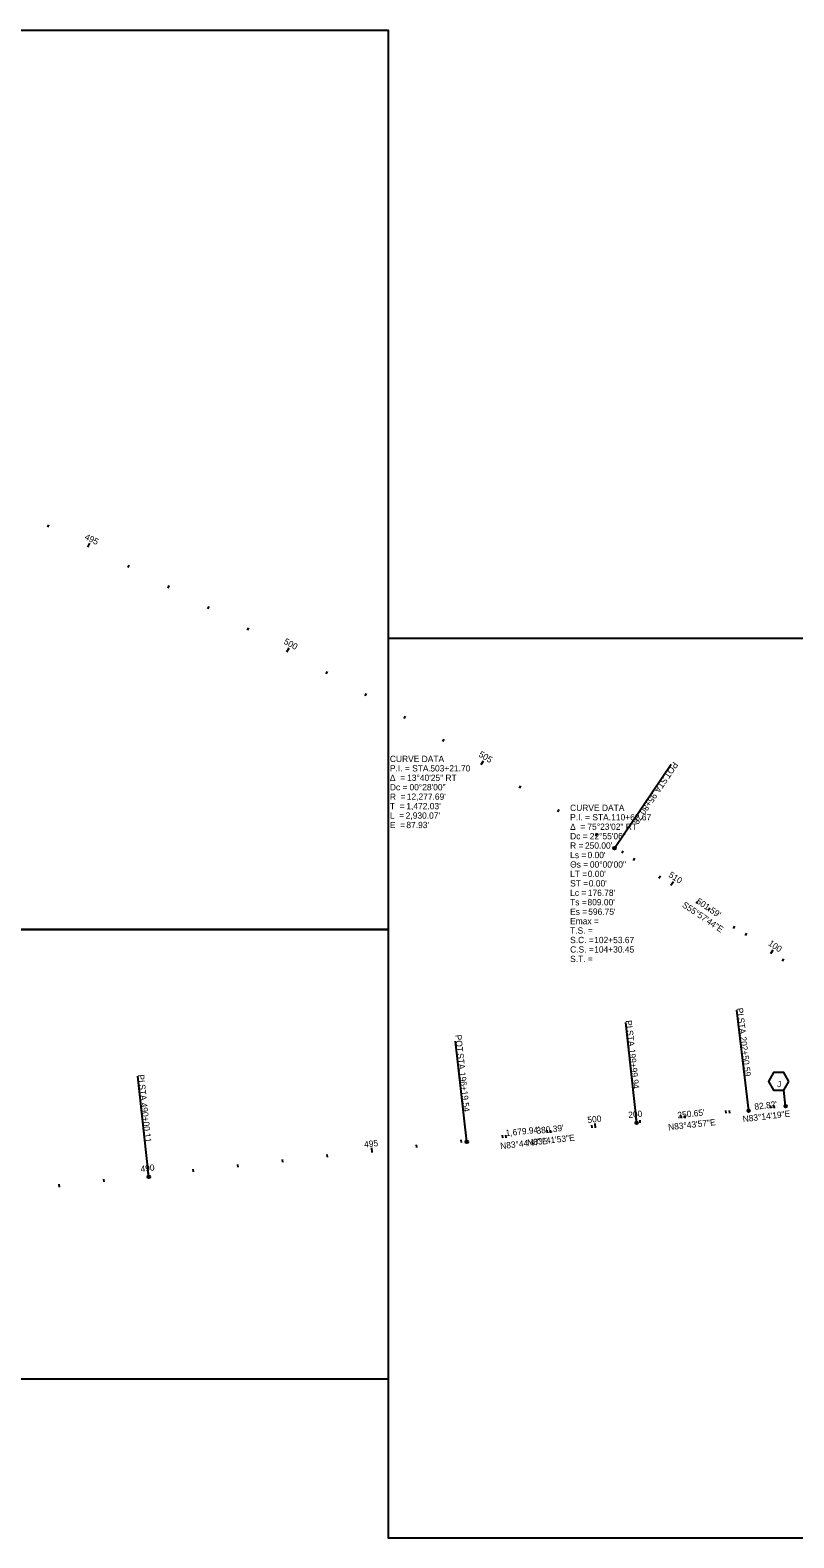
# Model space of a CAD drawing. Extents: x 1597353 to 1604853, y 283653 to 289007.
# Drawn here: x 1599057 to 1600756, y 285653 to 289007 of the extents above; entities that cross this region are included whole.
import ezdxf

# ---------------------------------------------------------------- set-up
doc = ezdxf.new("R2010")
doc.units = 0
for name, color, linetype in [('_CIVIL_CONSTRUCTION', 7, 'Continuous'), ('GE_X_Alignment_100_Cardinal_Points', 7, 'Continuous'), ('GE_X_Alignment_100_Curve_Data', 7, 'Continuous'), ('GE_X_Alignment_100_Distances', 7, 'Continuous'), ('GE_X_Alignment_100_Stations', 7, 'Continuous'), ('SH_Border', 7, 'Continuous'), ('SH_Cut_Line', 7, 'Continuous'), ('SH_Data', 7, 'Continuous'), ('SH_Masking', 7, 'Continuous'), ('SH_Named_Boundary', 7, 'Continuous'), ('SH_Text', 7, 'Continuous'), ('SV_X_Control_Cells_Found', 7, 'Continuous')]:
    doc.layers.add(name, color=color, linetype=linetype)

msp = doc.modelspace()

# ---------------------------------------------------------------- linework, layer by layer
at = {"layer": '_CIVIL_CONSTRUCTION'}
msp.add_line((1599853.4, 286006.5), (1597353.4, 286006.5), dxfattribs=at)
for points in [[(1597353.4, 289006.5), (1599853.4, 289006.5), (1599853.4, 287006.5), (1597353.4, 287006.5)], [(1599853.4, 287653.4), (1599853.4, 285653.4), (1600103.4, 285653.4), (1600353.4, 285653.4), (1600603.4, 285653.4), (1600853.4, 285653.4), (1601103.4, 285653.4), (1601353.4, 285653.4), (1601603.4, 285653.4), (1601853.4, 285653.4), (1602103.4, 285653.4), (1602353.4, 285653.4), (1602353.4, 287653.4), (1602103.4, 287653.4), (1601853.4, 287653.4), (1601603.4, 287653.4), (1601353.4, 287653.4), (1601103.4, 287653.4), (1600853.4, 287653.4), (1600603.4, 287653.4), (1600353.4, 287653.4), (1600103.4, 287653.4)]]:
    msp.add_lwpolyline(points, close=True, dxfattribs=at)
msp.add_lwpolyline([(1597353.4, 286006.5), (1597353.4, 287006.5), (1599853.4, 287006.5), (1599853.4, 286006.5)], dxfattribs=at)
at = {"layer": 'GE_X_Alignment_100_Curve_Data'}
msp.add_line((1599320.8, 286456.2), (1599296.3, 286679.9), dxfattribs=at)
msp.add_circle((1599320.8, 286456.2), 3, dxfattribs=at)
at = {"layer": 'GE_X_Alignment_100_Stations'}
for p, q in [((1599095.7, 287901.1), (1599098.3, 287906.5)), ((1599185.3, 287856.7), (1599189.8, 287865.7)), ((1599274.5, 287811.6), (1599277.3, 287816.9)), ((1599363.4, 287765.7), (1599366.2, 287771.1)), ((1599451.9, 287719.2), (1599454.7, 287724.5)), ((1599540, 287671.9), (1599542.9, 287677.1)), ((1599627.7, 287623.9), (1599632.6, 287632.6)), ((1599715.1, 287575.1), (1599718, 287580.4)), ((1599802, 287525.7), (1599805, 287530.9)), ((1599888.5, 287475.6), (1599891.5, 287480.7)), ((1599974.6, 287424.7), (1599977.7, 287429.9)), ((1600060.3, 287373.2), (1600065.5, 287381.7)), ((1600145.6, 287320.9), (1600148.7, 287326)), ((1600230.4, 287268), (1600233.6, 287273.1)), ((1600314.8, 287214.4), (1600318.1, 287219.4)), ((1600398.8, 287160.1), (1600402.1, 287165.1)), ((1600482.3, 287105.1), (1600487.9, 287113.4)), ((1600565.4, 287049.4), (1600568.8, 287054.4)), ((1600648, 286993.1), (1600651.4, 286998)), ((1600730.2, 286936.1), (1600733.6, 286941)), ((1600613, 286597.8), (1600612.3, 286603.7)), ((1600712.4, 286608.7), (1600711.7, 286614.6)), ((1600314.8, 286565.1), (1600313.7, 286575)), ((1600414.2, 286576), (1600413.5, 286582)), ((1600513.6, 286586.9), (1600512.9, 286592.9)), ((1600016.6, 286532.4), (1600015.9, 286538.4)), ((1600116, 286543.3), (1600115.3, 286549.3)), ((1600215.4, 286554.2), (1600214.7, 286560.2)), ((1599718.3, 286499.7), (1599717.7, 286505.7)), ((1599817.8, 286510.6), (1599816.7, 286520.6)), ((1599917.2, 286521.5), (1599916.5, 286527.5)), ((1599320.7, 286456.2), (1599319.6, 286466.1)), ((1599420.1, 286467.1), (1599419.5, 286473)), ((1599519.5, 286478), (1599518.9, 286483.9)), ((1599618.9, 286488.9), (1599618.3, 286494.8)), ((1599122, 286433.6), (1599121.3, 286439.6)), ((1599221.4, 286444.9), (1599220.7, 286450.9))]:
    msp.add_line(p, q, dxfattribs=at)
at = {"layer": 'SH_Border'}
for p, q in [((1600356.9, 287187.3), (1600482.8, 287373.8)), ((1600406.1, 286576.1), (1600381.6, 286799.7)), ((1600655.3, 286603.4), (1600628.8, 286826.9)), ((1600028, 286534.3), (1600003.3, 286758)), ((1600737.5, 286613.2), (1600733.3, 286648.7))]:
    msp.add_line(p, q, dxfattribs=at)
msp.add_lwpolyline([(1600744.6, 286668.3), (1600733.3, 286688), (1600710.6, 286688), (1600699.3, 286668.3), (1600710.6, 286648.7), (1600733.3, 286648.7)], close=True, dxfattribs=at)
for centre in [(1600356.9, 287187.3), (1600655.3, 286603.4), (1600406.1, 286576.1), (1600028, 286534.3)]:
    msp.add_circle(centre, 3, dxfattribs=at)
at = {"layer": 'SH_Text'}
for p, q in [((1600372.8, 287176.6), (1600376.2, 287181.5)), ((1600455.7, 287120.6), (1600459, 287125.6)), ((1600538.5, 287064.6), (1600541.9, 287069.6)), ((1600621.4, 287008.6), (1600624.8, 287013.6)), ((1600704.3, 286952.7), (1600709.9, 286961)), ((1600605, 286597.9), (1600604.3, 286603.9)), ((1600704.4, 286609.2), (1600703.6, 286615.2)), ((1600306.8, 286565.1), (1600306.1, 286571.1)), ((1600406.2, 286576.1), (1600405.1, 286586)), ((1600505.6, 286587), (1600504.9, 286593)), ((1600108, 286543.1), (1600107.3, 286549.1)), ((1600207.4, 286554.1), (1600206.7, 286560.1))]:
    msp.add_line(p, q, dxfattribs=at)
at = {"layer": 'SV_X_Control_Cells_Found'}
msp.add_circle((1600737.5, 286613.2), 3, dxfattribs=at)

# ---------------------------------------------------------------- texts
at = {"layer": 'GE_X_Alignment_100_Cardinal_Points'}
msp.add_text('N83°44\'47"E', height=14, rotation=6.2535, dxfattribs=at).set_placement((1600103.2, 286517.8))
at = {"layer": 'GE_X_Alignment_100_Curve_Data'}
for s, p in [('PI', (1599296.2, 286683.1)), (' STA. ', (1599298, 286666.6)), ('490+00.11', (1599303, 286620.3))]:
    msp.add_text(s, height=14, rotation=276.2535, dxfattribs=at).set_placement(p)
at = {"layer": 'GE_X_Alignment_100_Distances'}
msp.add_text("1,679.94'", height=14, rotation=6.2535, dxfattribs=at).set_placement((1600115.2, 286546.4))
at = {"layer": 'GE_X_Alignment_100_Stations'}
for s, rotation, p in [('495', 333.408, (1599176.6, 287875.1)), ('500', 331.0747, (1599619.5, 287642.7)), ('505', 328.7414, (1600053.1, 287392.2)), ('510', 326.4081, (1600475.6, 287124.5)), ('500', 6.2535, (1600297.2, 286575.8)), ('495', 6.2535, (1599800.4, 286521.3)), ('490', 6.4702, (1599303.1, 286466.8))]:
    msp.add_text(s, height=14, rotation=rotation, dxfattribs=at).set_placement(p)
at = {"layer": 'SH_Border'}
for s, rotation, p in [('POT', 235.9623, (1600487.7, 287380.6)), (' STA. ', 235.9623, (1600467.5, 287350.7)), ('95+80.78', 235.9623, (1600441.1, 287311.6)), ('PI', 276.7614, (1600628.5, 286831.2)), ('PI', 276.2675, (1600381.3, 286803.8)), (' STA. ', 276.7614, (1600630.5, 286814.4)), ('POT', 276.3018, (1600002.1, 286771.5)), (' STA. ', 276.2675, (1600383.2, 286787)), ('202+50.59', 276.7614, (1600636, 286767.4)), (' STA. ', 276.3018, (1600006, 286735.7)), ('199+99.94', 276.2675, (1600388.3, 286740)), ('196+19.54', 276.3018, (1600011.2, 286688.8))]:
    msp.add_text(s, height=14, rotation=rotation, dxfattribs=at).set_placement(p)
msp.add_text('J', height=14, dxfattribs=at).set_placement((1600718.5, 286655.7))
at = {"layer": 'SH_Cut_Line'}
for s, rotation, p in [('S55°57\'44"E', 325.9623, (1600505.9, 287057.7)), ('N83°14\'19"E', 6.7614, (1600642.8, 286577.8)), ('N83°43\'57"E', 6.2675, (1600476.8, 286559.7)), ('N83°41\'53"E', 6.3018, (1600163.2, 286525.1))]:
    msp.add_text(s, height=14, rotation=rotation, dxfattribs=at).set_placement(p)
at = {"layer": 'SH_Data'}
for s, p in [('CURVE DATA', (1600258, 287270)), ('Δ  = ', (1600258, 287228)), ('P.I. = STA. ', (1600258, 287249)), ('75°23\'02" RT', (1600296.4, 287228)), ('110+62.67', (1600349.4, 287249)), ('Dc = ', (1600258, 287207)), ('R = ', (1600258, 287186)), ("250.00'", (1600291, 287186)), ('22°55\'06"', (1600301.7, 287207)), ('Ls = ', (1600258, 287165)), ("0.00'", (1600296.8, 287165)), ('Θs = ', (1600258, 287144)), ('LT = ', (1600258, 287123)), ("0.00'", (1600297.3, 287123)), ('00°00\'00"', (1600302, 287144)), ('ST = ', (1600258, 287102)), ("0.00'", (1600299.6, 287102)), ('Ts = ', (1600258, 287060)), ('Lc = ', (1600258, 287081)), ("809.00'", (1600296.7, 287060)), ("176.78'", (1600297.4, 287081)), ('Es = ', (1600258, 287039)), ('Emax = ', (1600258, 287018)), ("596.75'", (1600298.3, 287039)), ('T.S. = ', (1600258, 286997)), ('S.C. = ', (1600258, 286976)), ('C.S. = ', (1600258, 286955)), ('102+53.67', (1600311.6, 286976)), ('104+30.45', (1600311.6, 286955)), ('S.T. = ', (1600258, 286934))]:
    msp.add_text(s, height=14, dxfattribs=at).set_placement(p)
at = {"layer": 'SH_Masking'}
for s, rotation, p in [("501.59'", 325.9623, (1600537.1, 287065.8)), ("250.65'", 6.2675, (1600497.5, 286586.3)), ("82.82'", 6.7614, (1600668.8, 286605.2)), ("380.39'", 6.3018, (1600183.9, 286551.7))]:
    msp.add_text(s, height=14, rotation=rotation, dxfattribs=at).set_placement(p)
at = {"layer": 'SH_Named_Boundary'}
for s, p in [('CURVE DATA', (1599857, 287378.8)), ('P.I. = STA. ', (1599857, 287357.8)), ('503+21.70', (1599947, 287357.8)), ('Δ  = ', (1599857, 287336.8)), ('13°40\'25" RT', (1599895.3, 287336.8)), ('Dc = ', (1599857, 287315.8)), ('R  = ', (1599857, 287294.8)), ("12,277.69'", (1599894.7, 287294.8)), ('00°28\'00"', (1599900.7, 287315.8)), ('T  = ', (1599857, 287273.8)), ('L  = ', (1599857, 287252.8)), ("2,930.07'", (1599892.2, 287252.8)), ("1,472.03'", (1599893.6, 287273.8)), ('E  = ', (1599857, 287231.8)), ("87.93'", (1599893.7, 287231.8))]:
    msp.add_text(s, height=14, dxfattribs=at).set_placement(p)
at = {"layer": 'SH_Text'}
for s, rotation, p in [('100', 325.9623, (1600697.4, 286972.4)), ('200', 6.2675, (1600388.2, 286586.7))]:
    msp.add_text(s, height=14, rotation=rotation, dxfattribs=at).set_placement(p)

doc.saveas('drawing.dxf')
